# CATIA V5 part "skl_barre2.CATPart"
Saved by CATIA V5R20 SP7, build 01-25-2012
Part number: skl_barre2
Publications: "axe_pivot_2_4", "axe_pivot_2_3", "axe_pivot_2_1", "PointB", "PointC", "PointE", "PlanRef"
Bounding box of the stored display mesh (mm): x 0 to 20, y -0.087 to 365.434, z -31.191 to 323.037
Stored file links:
  U:\Projet IAO\omeyer\Catia\skl_barre2.CATPart
  U:\Projet IAO\omeyer\Catia\skl_748.CATProduct
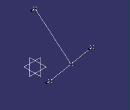
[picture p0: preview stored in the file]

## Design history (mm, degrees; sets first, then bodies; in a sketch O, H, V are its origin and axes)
Set1
  Point1 "PointB": linked copy from another document
  DatumPoint1 "PointC": linked copy from another document
  Point2 "PointM": linked copy from another document
  DatumPoint2 "PointE": linked copy from another document
  Plane1 "PlanRef": linked copy from another document
Set2
  Line1: type PtPt, FirstPoint Point1, SecondPoint DatumPoint1
  Line2: type PtPt, FirstPoint Point2, SecondPoint DatumPoint2
  Line3 "axe_pivot_2_1": type Normal, RefPoint Point1, RefSkin Plane1, Start 0, End 20
  Line4 "axe_pivot_2_3": type Normal, RefPoint DatumPoint1, RefSkin Plane1, Start 0, End 20
  Line5 "axe_pivot_2_4": type Normal, RefPoint DatumPoint2, RefSkin Plane1, Start 0, End 20
Body1 (main body)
